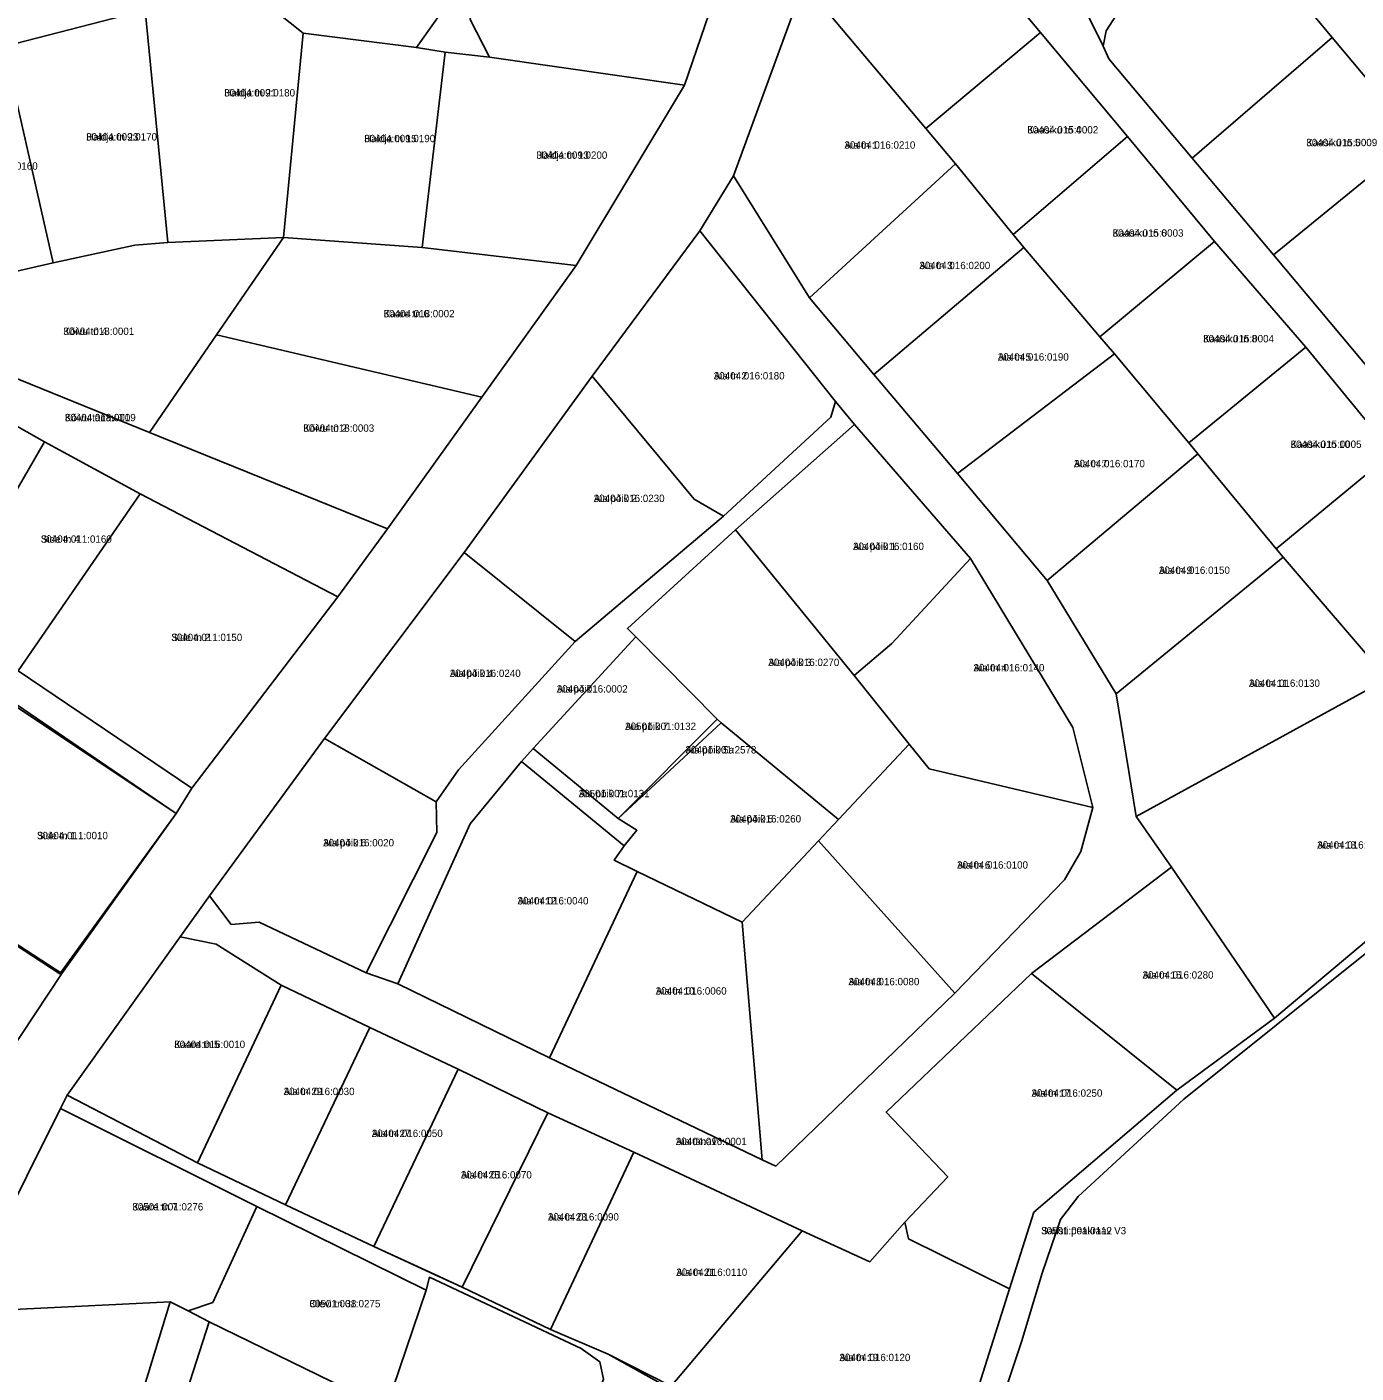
# Model space of a CAD drawing. Extents: x 542681 to 554572, y 6566489 to 6580482.
# Drawn here: x 544262.4 to 544534.3, y 6576162.5 to 6576437.8 of the extents above; entities that cross this region are included whole.
import ezdxf

# ---------------------------------------------------------------- set-up
doc = ezdxf.new("R2010")
doc.units = 0
for name, color, linetype in [('L_AADRESS', 7, 'Continuous'), ('PIIR', 7, 'Continuous'), ('TUNNUS', 7, 'Continuous')]:
    doc.layers.add(name, color=color, linetype=linetype)

msp = doc.modelspace()

# ---------------------------------------------------------------- linework, layer by layer
at = {"layer": 'PIIR'}
for points in [[(544555.69, 6576541.36), (544561.27, 6576535.5), (544538.06, 6576515.81), (544522.07, 6576500.46), (544514.92, 6576490.49), (544517.33, 6576488.57), (544504.72, 6576465.34), (544502.84, 6576467.59), (544483.23, 6576437.07), (544482.6, 6576433.94), (544477.04, 6576445.17), (544479.4, 6576446.61), (544481.19, 6576449.49), (544498.04, 6576476.42), (544513.48, 6576501.6), (544534.27, 6576521.01)], [(544536.66, 6576473.22), (544556.36, 6576450.94), (544570.95, 6576464), (544574.99, 6576458.71), (544589.57, 6576439.61), (544598.37, 6576427.81), (544595.17, 6576424.36), (544614.57, 6576393.64), (544587.01, 6576366.82), (544571.75, 6576385.09), (544546.67, 6576415.12), (544529.47, 6576435.7), (544504.72, 6576465.34), (544517.33, 6576488.57)], [(544304.24, 6576454.05), (544319.1, 6576470.25), (544350.51, 6576464.08), (544346.74, 6576440.15), (544342.09, 6576433.61), (544318.92, 6576436.54), (544313.58, 6576440.78)], [(544429.03, 6576466.28), (544445.62, 6576459.62), (544451.33, 6576458.67), (544469.74, 6576436.73), (544446.29, 6576417.06), (544421.34, 6576446.76), (544420.89, 6576447.56)], [(544500.83, 6576410.98), (544483.77, 6576431.35), (544482.6, 6576433.94), (544483.23, 6576437.07), (544502.84, 6576467.59), (544504.72, 6576465.34), (544529.47, 6576435.7)], [(544353.09, 6576439.33), (544356.52, 6576462.51), (544406.15, 6576452.84), (544396.94, 6576425.92), (544357.08, 6576431.65)], [(544291.27, 6576393.78), (544286.61, 6576441.29), (544304.24, 6576454.05), (544313.58, 6576440.78), (544318.92, 6576436.54), (544314.88, 6576394.77)], [(544446.29, 6576417.06), (544452.37, 6576409.83), (544422.48, 6576382.45), (544406.96, 6576407.35), (544421.34, 6576446.76)], [(544257.79, 6576433.83), (544286.61, 6576441.29), (544291.27, 6576393.78), (544284.48, 6576393.2), (544267.8, 6576389.6)], [(544314.88, 6576394.77), (544318.92, 6576436.54), (544342.09, 6576433.61), (544347.98, 6576432.67), (544343.28, 6576392.72)], [(544452.37, 6576409.83), (544446.29, 6576417.06), (544469.74, 6576436.73), (544487.54, 6576415.42), (544464.16, 6576395.37)], [(544546.67, 6576415.12), (544517.45, 6576391.19), (544500.83, 6576410.98), (544529.47, 6576435.7)], [(544232.45, 6576382.15), (544235.52, 6576429.45), (544242.57, 6576429.7), (544257.79, 6576433.83), (544267.8, 6576389.6), (544238.95, 6576382.96)], [(544343.28, 6576392.72), (544347.98, 6576432.67), (544357.08, 6576431.65), (544396.94, 6576425.92), (544374.75, 6576389.06)], [(544487.54, 6576415.42), (544505.38, 6576393.92), (544481.91, 6576374.46), (544466.33, 6576392.7), (544464.16, 6576395.37)], [(544571.75, 6576385.09), (544543.07, 6576360.6), (544517.45, 6576391.19), (544546.67, 6576415.12)], [(544452.37, 6576409.83), (544464.16, 6576395.37), (544466.33, 6576392.7), (544435.64, 6576366.77), (544422.48, 6576382.45)], [(544406.96, 6576407.35), (544422.48, 6576382.45), (544435.64, 6576366.77), (544452.82, 6576346.49), (544471.15, 6576324.59), (544485.27, 6576301.42), (544489.36, 6576276.33), (544496.54, 6576265.96), (544467.94, 6576244.2), (544438.17, 6576215.87), (544450.78, 6576202.6), (544442.01, 6576193.33), (544434.83, 6576185.24), (544421, 6576191.6), (544386.58, 6576207.68), (544369.01, 6576215.73), (544350.65, 6576224.65), (544332.6, 6576233.15), (544314.44, 6576241.81), (544301.14, 6576250.24), (544293.78, 6576251.73), (544299.79, 6576260.11), (544304.22, 6576254.26), (544309.9, 6576254.69), (544331.79, 6576244.32), (544338.29, 6576242.12), (544369.31, 6576226.94), (544412.81, 6576206.09), (544415.64, 6576204.81), (544452.26, 6576240.19), (544474.71, 6576263.37), (544478, 6576269.17), (544480.5, 6576278.19), (544476.39, 6576294.51), (544455.45, 6576329.12), (544431.73, 6576356.49), (544427.81, 6576361.24), (544400.08, 6576396.12)], [(544378.02, 6576366.4), (544400.08, 6576396.12), (544427.81, 6576361.24), (544426.86, 6576358.01), (544404.89, 6576337.76), (544398.89, 6576341.24)], [(544232.45, 6576382.15), (544238.95, 6576382.96), (544267.8, 6576389.6), (544284.48, 6576393.2), (544291.27, 6576393.78), (544314.88, 6576394.77), (544301.19, 6576374.86), (544287.46, 6576354.91), (544238.75, 6576374.62)], [(544314.88, 6576394.77), (544343.28, 6576392.72), (544374.75, 6576389.06), (544355.46, 6576362.13), (544301.19, 6576374.86)], [(544484.9, 6576370.95), (544481.91, 6576374.46), (544505.38, 6576393.92), (544524.05, 6576372.36), (544500.12, 6576352.74)], [(544210.63, 6576393.14), (544232.45, 6576382.15), (544238.75, 6576374.62), (544287.46, 6576354.91), (544336.17, 6576335.2), (544326.02, 6576321.24), (544285.57, 6576342.34), (544265.98, 6576352.98), (544242.72, 6576366.15), (544220.47, 6576376.55), (544205.21, 6576384.66), (544207.76, 6576388.65)], [(544466.33, 6576392.7), (544481.91, 6576374.46), (544484.9, 6576370.95), (544452.82, 6576346.49), (544435.64, 6576366.77)], [(544301.19, 6576374.86), (544355.46, 6576362.13), (544336.17, 6576335.2), (544287.46, 6576354.91)], [(544524.05, 6576372.36), (544541.75, 6576350.72), (544518, 6576331.1), (544501.98, 6576350.5), (544500.12, 6576352.74)], [(544484.9, 6576370.95), (544500.12, 6576352.74), (544501.98, 6576350.5), (544471.15, 6576324.59), (544452.82, 6576346.49)], [(544242.72, 6576366.15), (544265.98, 6576352.98), (544244.97, 6576316.55), (544229.17, 6576321.66)], [(544351.85, 6576330.35), (544378.02, 6576366.4), (544398.89, 6576341.24), (544404.89, 6576337.76), (544374.58, 6576312.13)], [(544426.86, 6576358.01), (544427.81, 6576361.24), (544431.73, 6576356.49), (544407.38, 6576334.94), (544385.26, 6576314.77), (544387, 6576313.08), (544366.01, 6576290.24), (544363.62, 6576287.57), (544353.11, 6576274.8), (544338.29, 6576242.12), (544331.79, 6576244.32), (544346.26, 6576273.04), (544346.17, 6576279.35), (544350.73, 6576285.85), (544374.58, 6576312.13), (544404.89, 6576337.76)], [(544407.38, 6576334.94), (544431.73, 6576356.49), (544455.45, 6576329.12), (544439.33, 6576311.7), (544431.65, 6576305.18)], [(544244.97, 6576316.55), (544265.98, 6576352.98), (544285.57, 6576342.34), (544260.61, 6576306.15)], [(544501.98, 6576350.5), (544518, 6576331.1), (544519.42, 6576329.38), (544485.27, 6576301.42), (544471.15, 6576324.59)], [(544541.75, 6576350.72), (544560.53, 6576328.52), (544568.17, 6576321.98), (544544.18, 6576300.5), (544540.79, 6576304.47), (544519.42, 6576329.38), (544518, 6576331.1)], [(544285.57, 6576342.34), (544326.02, 6576321.24), (544296.12, 6576282.1), (544260.61, 6576306.15)], [(544428.43, 6576275.71), (544404.45, 6576295.48), (544403.6, 6576296.22), (544387, 6576313.08), (544385.27, 6576314.76), (544407.38, 6576334.94), (544431.65, 6576305.18), (544442.92, 6576291.14)], [(544374.58, 6576312.13), (544350.73, 6576285.85), (544346.17, 6576279.35), (544323.29, 6576292.31), (544351.85, 6576330.35)], [(544442.92, 6576291.14), (544431.65, 6576305.18), (544439.33, 6576311.7), (544455.45, 6576329.12), (544476.39, 6576294.51), (544480.5, 6576278.19), (544446.97, 6576286.08)], [(544519.42, 6576329.38), (544540.79, 6576304.47), (544489.36, 6576276.33), (544485.27, 6576301.42)], [(544383.39, 6576275.95), (544366.01, 6576290.24), (544387, 6576313.08), (544403.6, 6576296.22)], [(544489.36, 6576276.33), (544540.79, 6576304.47), (544544.18, 6576300.5), (544565.08, 6576275.99), (544565.56, 6576275.4), (544517.64, 6576235.05), (544496.54, 6576265.96)], [(544235.91, 6576265.86), (544257.08, 6576297.28), (544260.3, 6576299.22), (544292.94, 6576276.91), (544269.12, 6576244.14)], [(544382.57, 6576267.38), (544384.58, 6576270.32), (544387.22, 6576273.5), (544383.39, 6576275.95), (544404.45, 6576295.48), (544428.43, 6576275.71), (544424.33, 6576271.33), (544408.72, 6576254.71), (544387.28, 6576265.11)], [(544383.39, 6576275.95), (544403.6, 6576296.22), (544404.45, 6576295.48)], [(544304.22, 6576254.26), (544299.79, 6576260.11), (544323.29, 6576292.31), (544346.17, 6576279.35), (544346.26, 6576273.04), (544331.79, 6576244.32), (544309.9, 6576254.69)], [(544384.58, 6576270.32), (544363.62, 6576287.57), (544366.01, 6576290.24), (544383.39, 6576275.95), (544387.22, 6576273.5)], [(544428.43, 6576275.71), (544442.92, 6576291.14), (544446.97, 6576286.08), (544480.5, 6576278.19), (544478, 6576269.17), (544474.71, 6576263.37), (544452.26, 6576240.19), (544424.33, 6576271.33)], [(544353.11, 6576274.8), (544363.62, 6576287.57), (544384.58, 6576270.32), (544382.57, 6576267.38), (544387.28, 6576265.11), (544369.31, 6576226.94), (544338.29, 6576242.12)], [(544412.81, 6576206.09), (544408.72, 6576254.71), (544424.33, 6576271.33), (544452.26, 6576240.19), (544415.64, 6576204.81)], [(544222.23, 6576214.33), (544200.17, 6576227.79), (544213.15, 6576236.23), (544221.29, 6576243.85), (544228.15, 6576253.42), (544236.27, 6576265.82), (544269.55, 6576244.2), (544241.94, 6576202.52)], [(544387.28, 6576265.11), (544408.72, 6576254.71), (544412.81, 6576206.09), (544369.31, 6576226.94)], [(544467.94, 6576244.2), (544496.54, 6576265.96), (544517.64, 6576235.05), (544497.68, 6576220.38)], [(544270.66, 6576219.33), (544293.78, 6576251.73), (544301.14, 6576250.24), (544314.44, 6576241.81), (544297.28, 6576205.48)], [(544297.28, 6576205.48), (544314.44, 6576241.81), (544332.6, 6576233.15), (544315.32, 6576196.92)], [(544438.17, 6576215.87), (544467.94, 6576244.2), (544497.68, 6576220.38), (544468.42, 6576195.36), (544463.43, 6576179.69), (544442.75, 6576189.94), (544442.01, 6576193.33), (544450.78, 6576202.6)], [(544333.39, 6576188.35), (544315.32, 6576196.92), (544332.6, 6576233.15), (544350.65, 6576224.65)], [(544333.39, 6576188.35), (544350.65, 6576224.65), (544369.01, 6576215.73), (544351.47, 6576180.06), (544345.07, 6576182.99)], [(544291.75, 6576177.06), (544248.48, 6576174.91), (544269.27, 6576216.57), (544309.48, 6576196.57), (544300.42, 6576176.92), (544295.43, 6576175.19)], [(544369.53, 6576171.4), (544351.47, 6576180.06), (544369.01, 6576215.73), (544386.58, 6576207.68)], [(544421, 6576191.6), (544394.2, 6576159.83), (544381.29, 6576166.31), (544369.53, 6576171.4), (544386.58, 6576207.68)], [(544299.73, 6576172.96), (544295.43, 6576175.19), (544300.42, 6576176.92), (544309.48, 6576196.57), (544344.06, 6576179.43), (544335.91, 6576155.29)], [(544434.83, 6576185.24), (544442.01, 6576193.33), (544442.75, 6576189.94), (544463.43, 6576179.69), (544449.82, 6576136.52), (544394.2, 6576159.83), (544421, 6576191.6)], [(544344.06, 6576179.43), (544344.75, 6576182.07), (544375.81, 6576167.47), (544379.6, 6576164.76), (544380.36, 6576161.26), (544372.71, 6576142.68), (544369.28, 6576138.91), (544335.58, 6576154.14), (544335.91, 6576155.29)], [(544240.49, 6576158.91), (544248.48, 6576174.91), (544291.75, 6576177.06), (544280.65, 6576140.9)], [(544335.58, 6576154.14), (544330.6, 6576136.26), (544328.89, 6576129.9), (544291.15, 6576146.53), (544299.73, 6576172.96), (544335.91, 6576155.29)]]:
    msp.add_lwpolyline(points, close=True, dxfattribs=at)
for points in [[(544541.75, 6576350.72), (544524.05, 6576372.36), (544505.38, 6576393.92), (544487.54, 6576415.42), (544469.74, 6576436.73), (544451.33, 6576458.67), (544445.62, 6576459.62), (544429.03, 6576466.28), (544431.24, 6576474.73), (544451.09, 6576468.39), (544450.26, 6576467.07), (544461.76, 6576459.32), (544473.86, 6576446.43), (544477.04, 6576445.17), (544482.6, 6576433.94), (544483.77, 6576431.35), (544500.83, 6576410.98), (544517.45, 6576391.19), (544543.07, 6576360.6)], [(544241.94, 6576202.52), (544269.55, 6576244.2), (544292.94, 6576276.91), (544296.12, 6576282.1), (544326.02, 6576321.24), (544336.17, 6576335.2), (544355.46, 6576362.13), (544374.75, 6576389.06), (544396.94, 6576425.92), (544406.15, 6576452.84)], [(544421.34, 6576446.76), (544406.96, 6576407.35), (544400.08, 6576396.12), (544378.02, 6576366.4), (544351.85, 6576330.35), (544323.29, 6576292.31), (544299.79, 6576260.11), (544293.78, 6576251.73), (544270.66, 6576219.33), (544269.27, 6576216.57), (544248.48, 6576174.91)], [(544286.61, 6576441.29), (544257.79, 6576433.83)], [(544353.09, 6576439.33), (544357.08, 6576431.65), (544347.98, 6576432.67), (544342.09, 6576433.61), (544346.74, 6576440.15)], [(544452.24, 6576128.05), (544465.86, 6576168.89), (544468.62, 6576177.96), (544470.13, 6576182.89), (544473.83, 6576193.9), (544477.5, 6576198.58), (544499.12, 6576218.53), (544536.54, 6576248.53), (544543.03, 6576253.68), (544605.71, 6576302.05), (544638.77, 6576328.89), (544648.04, 6576326.26), (544662.01, 6576322.38), (544726.99, 6576304.35), (544796.24, 6576285.13), (544827.15, 6576276.55), (544607.11, 6575483.32)], [(544260.61, 6576306.15), (544296.12, 6576282.1), (544292.94, 6576276.91), (544260.31, 6576298.73)], [(544449.82, 6576136.52), (544463.43, 6576179.69), (544468.42, 6576195.36), (544497.68, 6576220.38), (544517.64, 6576235.05), (544565.56, 6576275.4)], [(544536.54, 6576248.53), (544499.12, 6576218.53), (544477.5, 6576198.58), (544473.83, 6576193.9), (544470.13, 6576182.89), (544468.62, 6576177.96), (544465.86, 6576168.89), (544452.24, 6576128.05)], [(544380.36, 6576161.26), (544379.6, 6576164.76), (544375.81, 6576167.47), (544344.75, 6576182.07), (544344.06, 6576179.43), (544309.48, 6576196.57), (544269.27, 6576216.57), (544270.66, 6576219.33), (544297.28, 6576205.48), (544315.32, 6576196.92), (544333.39, 6576188.35), (544344.85, 6576183.09), (544351.47, 6576180.06), (544369.53, 6576171.4), (544381.29, 6576166.31), (544393.77, 6576159.4)], [(544280.65, 6576140.9), (544291.75, 6576177.06), (544295.43, 6576175.19), (544299.73, 6576172.96), (544291.15, 6576146.53)]]:
    msp.add_lwpolyline(points, dxfattribs=at)

# ---------------------------------------------------------------- texts
at = {"layer": 'L_AADRESS'}
for s, p in [('Haldja tn 21', (544302.77, 6576423.62)), ('Haldja tn 23', (544274.53, 6576414.61)), ('Haldja tn 15', (544331.43, 6576414.27)), ('Kaasiku tn 4', (544467.08, 6576416.05)), ('Aia tn 1', (544429.66, 6576412.94)), ('Kaasiku tn 5', (544524.16, 6576413.45)), ('Haldja tn 13', (544366.65, 6576410.87)), ('Kaasiku tn 6', (544484.52, 6576394.94)), ('Aia tn 3', (544444.99, 6576388.3)), ('Kaare tn 6', (544335.4, 6576378.45)), ('Kõivu tn 4', (544269.87, 6576374.84)), ('Kaasiku tn 8', (544503.04, 6576373.33)), ('Aia tn 5', (544461.05, 6576369.59)), ('Aia tn 2', (544402.92, 6576365.73)), ('Kõivu tänav T1', (544270.18, 6576357.19)), ('Kõivu tn 2', (544318.96, 6576355.03)), ('Kaasiku tn 10', (544520.94, 6576351.73)), ('Aia tn 7', (544476.62, 6576347.77)), ('Aia põik 2', (544378.37, 6576340.66)), ('Side tn 4', (544265.27, 6576332.33)), ('Aia põik 1', (544431.42, 6576330.84)), ('Aia tn 9', (544494.01, 6576325.96)), ('Side tn 2', (544291.96, 6576312.22)), ('Aia põik 3', (544414.1, 6576307.12)), ('Aia põik 4', (544348.93, 6576304.88)), ('Aia tn 4', (544456.07, 6576306.01)), ('Aia põik', (544370.81, 6576301.68)), ('Aia tn 11', (544512.43, 6576302.85)), ('Aia põik 7', (544384.8, 6576294.03)), ('Aia põik 5a', (544397.15, 6576289.22)), ('Aia põik 7a', (544375.3, 6576280.28)), ('Aia põik 5', (544406.29, 6576275.1)), ('Side tn 1', (544264.48, 6576271.68)), ('Aia põik 6', (544323.02, 6576270.21)), ('Aia tn 13', (544526.39, 6576269.76)), ('Aia tn 6', (544452.71, 6576265.67)), ('Aia tn 12', (544362.79, 6576258.34)), ('Aia tn 15', (544490.66, 6576243.17)), ('Aia tn 8', (544430.49, 6576241.81)), ('Aia tn 10', (544391.06, 6576239.9)), ('Kaare tn 5', (544292.55, 6576228.97)), ('Aia tn 29', (544314.94, 6576219.34)), ('Aia tn 17', (544467.93, 6576219)), ('Aia tn 27', (544332.98, 6576210.76)), ('Aia tänav', (544395.16, 6576209.11)), ('Aia tn 25', (544351.2, 6576202.28)), ('Kaare tn 7', (544283.99, 6576195.74)), ('Aia tn 23', (544369.02, 6576193.68)), ('Sausti peakraav V3', (544469.9, 6576190.86)), ('Aia tn 21', (544395.27, 6576182.36)), ('Olevi tn 38', (544320.22, 6576175.93)), ('Aia tn 19', (544428.64, 6576164.92))]:
    msp.add_text(s, height=1.5, dxfattribs=at).set_placement(p)
at = {"layer": 'TUNNUS'}
for s, p in [('30404:009:0180', (544302.77, 6576423.62)), ('30404:009:0170', (544274.53, 6576414.61)), ('30404:009:0190', (544331.43, 6576414.27)), ('30404:015:0002', (544467.08, 6576416.05)), ('30404:016:0210', (544429.66, 6576412.94)), ('30404:015:0009', (544524.16, 6576413.45)), ('30404:009:0160', (544250.12, 6576408.64)), ('30404:009:0200', (544366.65, 6576410.87)), ('30404:015:0003', (544484.52, 6576394.94)), ('30404:016:0200', (544444.99, 6576388.3)), ('30404:018:0002', (544335.4, 6576378.45)), ('30404:018:0001', (544269.87, 6576374.84)), ('30404:015:0004', (544503.04, 6576373.33)), ('30404:016:0190', (544461.05, 6576369.59)), ('30404:016:0180', (544402.92, 6576365.73)), ('30404:018:0009', (544270.18, 6576357.19)), ('30404:018:0003', (544318.96, 6576355.03)), ('30404:015:0005', (544520.94, 6576351.73)), ('30404:016:0170', (544476.62, 6576347.77)), ('30404:016:0230', (544378.37, 6576340.66)), ('30404:011:0160', (544265.27, 6576332.33)), ('30404:016:0160', (544431.42, 6576330.84)), ('30404:016:0150', (544494.01, 6576325.96)), ('30404:011:0150', (544291.96, 6576312.22)), ('30404:016:0270', (544414.1, 6576307.12)), ('30404:016:0240', (544348.93, 6576304.88)), ('30404:016:0140', (544456.07, 6576306.01)), ('30404:016:0002', (544370.81, 6576301.68)), ('30404:016:0130', (544512.43, 6576302.85)), ('30501:001:0132', (544384.8, 6576294.03)), ('30401:001:2578', (544397.15, 6576289.22)), ('30501:001:0131', (544375.3, 6576280.28)), ('30404:016:0260', (544406.29, 6576275.1)), ('30404:011:0010', (544264.48, 6576271.68)), ('30404:016:0020', (544323.02, 6576270.21)), ('30404:016:0220', (544526.39, 6576269.76)), ('30404:016:0100', (544452.71, 6576265.67)), ('30404:016:0040', (544362.79, 6576258.34)), ('30404:016:0280', (544490.66, 6576243.17)), ('30404:016:0080', (544430.49, 6576241.81)), ('30404:016:0060', (544391.06, 6576239.9)), ('30404:016:0010', (544292.55, 6576228.97)), ('30404:016:0030', (544314.94, 6576219.34)), ('30404:016:0250', (544467.93, 6576219)), ('30404:016:0050', (544332.98, 6576210.76)), ('30404:016:0001', (544395.16, 6576209.11)), ('30404:016:0070', (544351.2, 6576202.28)), ('30501:001:0276', (544283.99, 6576195.74)), ('30404:016:0090', (544369.02, 6576193.68)), ('30501:001:0112', (544469.9, 6576190.86)), ('30404:016:0110', (544395.27, 6576182.36)), ('30501:001:0275', (544320.22, 6576175.93)), ('30404:016:0120', (544428.64, 6576164.92))]:
    msp.add_text(s, height=1.5, dxfattribs=at).set_placement(p)

doc.saveas('drawing.dxf')
